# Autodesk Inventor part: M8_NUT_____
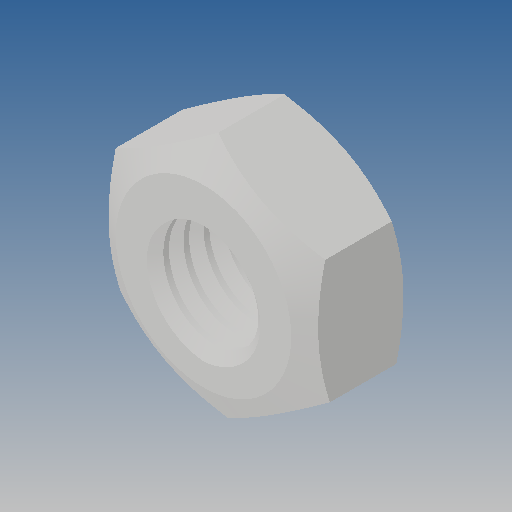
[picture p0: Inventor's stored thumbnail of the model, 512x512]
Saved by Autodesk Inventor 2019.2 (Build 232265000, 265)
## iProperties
Created: 2012-06
Part Number: M8_NUT_____
Material: Ogólny
Document SubType Name: Modeling
Designer: CADENGINEERING4
Density: 1 g/cm^3
Appearance: Domyślna
Author: CADENGINEERING4
Revision Number: 1LAST_VERSION
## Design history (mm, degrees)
feature "Baza1"
node "Bryła1"
